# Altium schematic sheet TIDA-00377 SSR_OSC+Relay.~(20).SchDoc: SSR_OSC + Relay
size 431 x 279 mm; Date: Not shown in title block; ApprovedBy: Not shown in title block; CheckedBy: Not shown in title block; Author: Not shown in title block; CompanyName: Not shown in title block; DrawnBy: Jarrod Krebs; Engineer: Not shown in title block; Organization: Not shown in title block; Address1: Not shown in title block; Address2: Not shown in title block; Address3: Not shown in title block; Address4: Not shown in title block; DocumentNumber: 1; Revision: Use project parameter SCH_Rev; SheetNumber: 2; SheetTotal: 3; PageSetup: Record=PageOptions¦CenterHorizontal=True¦CenterVertical=True¦PrintScale=0.62¦XCorrection=1.00¦YCorrection=1.00¦PrintKind=0¦BorderSize=5000000¦LeftOffset=0¦BottomOffset=0¦Orientation=2¦PaperLength=1000¦PaperWidth=1000¦Scale=100¦PaperSource=15¦PrintQuality=-3¦MediaType=1¦DitherType=10¦PrintScaleMode=1¦PaperKind=Letter¦PaperIndex=1
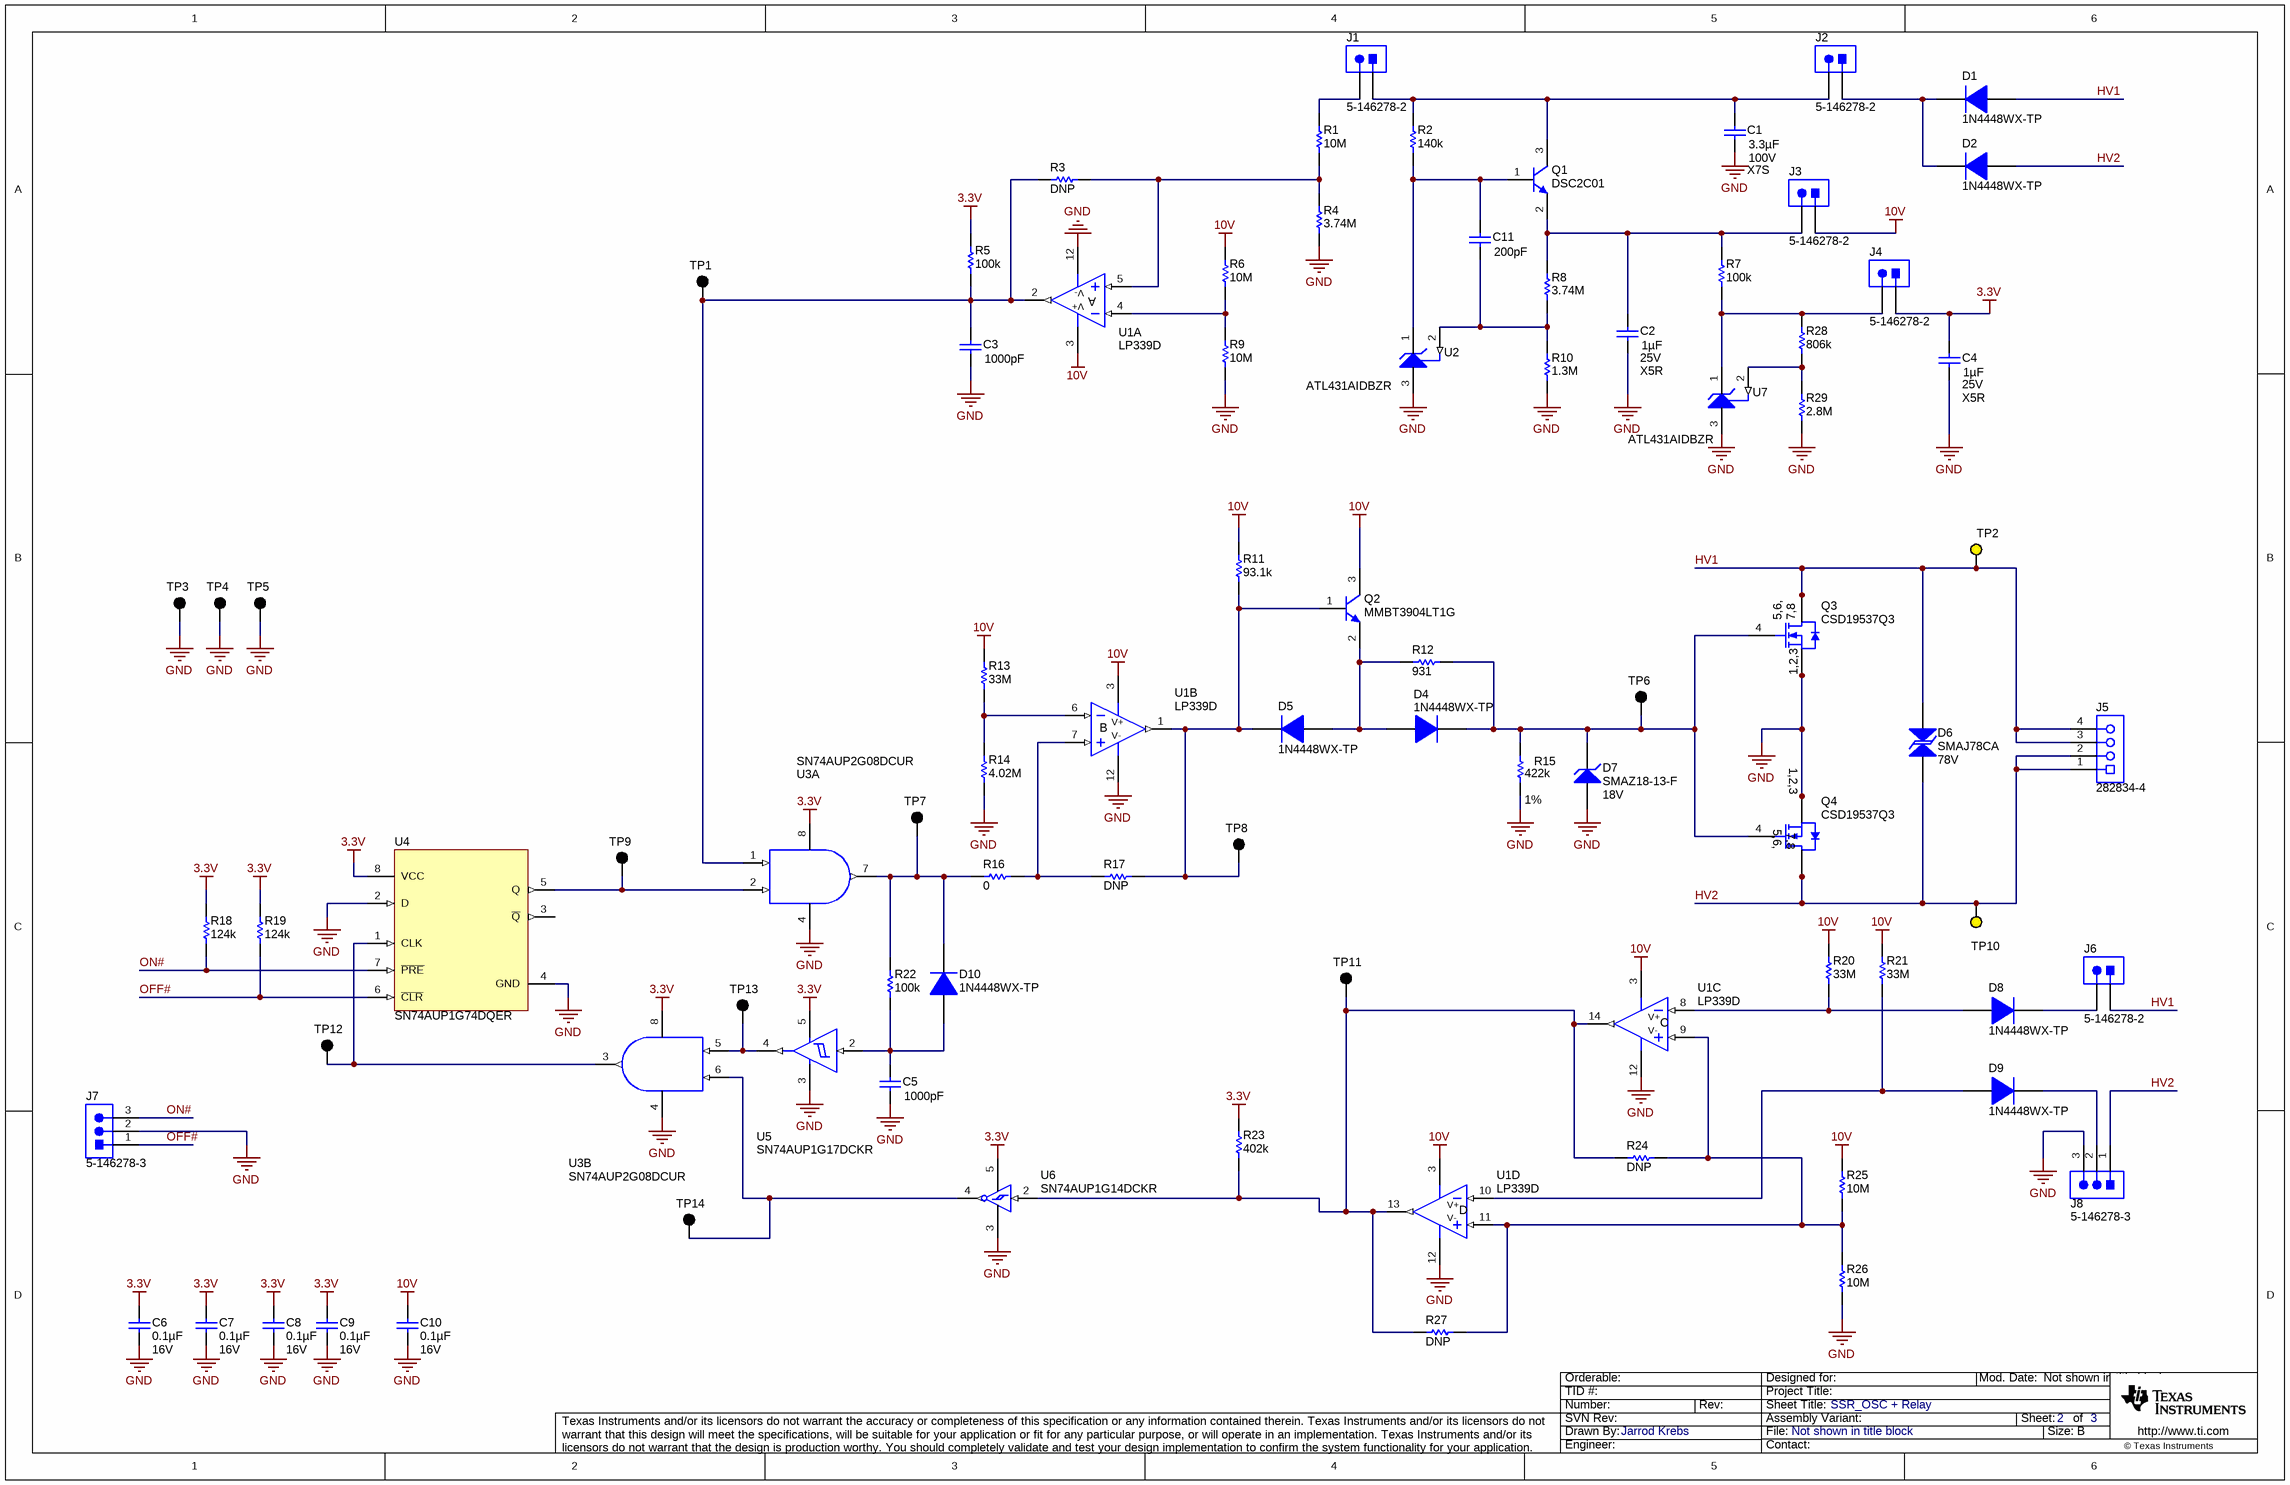
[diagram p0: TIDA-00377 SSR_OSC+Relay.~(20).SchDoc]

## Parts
C1  ValueDisplayed: 3.3µF  VDC_V: 100V  TempCo: X7S  [0603]  (hidden comment: GRM188R61E105KA12D)
C2  ValueDisplayed: 1µF  Value2: 25V  TempCo: X5R  [0603]  (hidden comment: GRM188R61E105KA12D)
C3  ValueDisplayed: 1000pF  [0603]  (hidden comment: GRM188R61E105KA12D)
C4  ValueDisplayed: 1µF  Value2: 25V  TempCo: X5R  [0603]  (hidden comment: GRM188R61E105KA12D)
C5  ValueDisplayed: 1000pF  [0603]  (hidden comment: GRM188R61E105KA12D)
C6  ValueDisplayed: 0.1µF  Value2: 16V  [0603]  (hidden comment: GRM188R71C104KA01D)
C7  ValueDisplayed: 0.1µF  Value2: 16V  [0603]  (hidden comment: GRM188R71C104KA01D)
C8  ValueDisplayed: 0.1µF  Value2: 16V  [0603]  (hidden comment: GRM188R71C104KA01D)
C9  ValueDisplayed: 0.1µF  Value2: 16V  [0603]  (hidden comment: GRM188R71C104KA01D)
C10  ValueDisplayed: 0.1µF  Value2: 16V  [0603]  (hidden comment: GRM188R71C104KA01D)
C11  ValueDisplayed: 200pF  [0603]  (hidden comment: GRM188R61E105KA12D)
D1  1N4448WX-TP  [sod-323]
D2  1N4448WX-TP  [sod-323]
D4  1N4448WX-TP  [sod-323]
D5  1N4448WX-TP  [sod-323]
D6  SMAJ78CA  value 78V  [SMA]
D7  SMAZ18-13-F  value 18V  [SMA]
D8  1N4448WX-TP  [sod-323]
D9  1N4448WX-TP  [sod-323]
D10  1N4448WX-TP  [sod-323]
J1  5-146278-2  [TE_5-146278-2]
J2  5-146278-2  [TE_5-146278-2]
J3  5-146278-2  [TE_5-146278-2]
J4  5-146278-2  [TE_5-146278-2]
J5  282834-4  [TEC_282834-4]
J6  5-146278-2  [TE_5-146278-2]
J7  5-146278-3  [TE_5-146278-3]
J8  5-146278-3  [TE_5-146278-3]
Q1  DSC2C01  [SOT-23]
Q2  MMBT3904LT1G  [SOT-23]
Q3  CSD19537Q3  [DQG0008A]
Q4  CSD19537Q3  [DQG0008A]
R1  ValueDisplayed: 10M  [0805_HV]  (hidden comment: CRCW08050000Z0EA)
R2  ValueDisplayed: 140k  [0805_HV]  (hidden comment: CRCW08050000Z0EA)
R3  ValueDisplayed: DNP  [0805_HV]  (hidden comment: CRCW08050000Z0EA)
R4  ValueDisplayed: 3.74M  [0805_HV]  (hidden comment: CRCW08050000Z0EA)
R5  ValueDisplayed: 100k  [0805_HV]  (hidden comment: CRCW08050000Z0EA)
R6  ValueDisplayed: 10M  [0805_HV]  (hidden comment: CRCW08050000Z0EA)
R7  ValueDisplayed: 100k  [0805_HV]  (hidden comment: CRCW08050000Z0EA)
R8  ValueDisplayed: 3.74M  [0805_HV]  (hidden comment: CRCW08050000Z0EA)
R9  ValueDisplayed: 10M  [0805_HV]  (hidden comment: CRCW08050000Z0EA)
R10  ValueDisplayed: 1.3M  [0805_HV]  (hidden comment: CRCW08050000Z0EA)
R11  ValueDisplayed: 93.1k  [0805_HV]  (hidden comment: CRCW08050000Z0EA)
R12  ValueDisplayed: 931  [0805_HV]  (hidden comment: CRCW08050000Z0EA)
R13  ValueDisplayed: 33M  [0805_HV]  (hidden comment: CRCW08050000Z0EA)
R14  ValueDisplayed: 4.02M  [0805_HV]  (hidden comment: CRCW08050000Z0EA)
R15  ValueDisplayed: 422k  Value1: 1%  [0805_HV]  (hidden comment: CRCW0805422KFKEA)
R16  ValueDisplayed: 0  [0805_HV]  (hidden comment: CRCW08050000Z0EA)
R17  ValueDisplayed: DNP  [0805_HV]  (hidden comment: CRCW08050000Z0EA)
R18  ValueDisplayed: 124k  [0402]  (hidden comment: CRCW0402100KJNED)
R19  ValueDisplayed: 124k  [0402]  (hidden comment: CRCW0402100KJNED)
R20  ValueDisplayed: 33M  [0805_HV]  (hidden comment: CRCW08050000Z0EA)
R21  ValueDisplayed: 33M  [0805_HV]  (hidden comment: CRCW08050000Z0EA)
R22  ValueDisplayed: 100k  [0805_HV]  (hidden comment: CRCW08050000Z0EA)
R23  ValueDisplayed: 402k  [0805_HV]  (hidden comment: CRCW08050000Z0EA)
R24  ValueDisplayed: DNP  [0805_HV]  (hidden comment: CRCW08050000Z0EA)
R25  ValueDisplayed: 10M  [0805_HV]  (hidden comment: CRCW08050000Z0EA)
R26  ValueDisplayed: 10M  [0805_HV]  (hidden comment: CRCW08050000Z0EA)
R27  ValueDisplayed: DNP  [0805_HV]  (hidden comment: CRCW08050000Z0EA)
R28  ValueDisplayed: 806k  [0805_HV]  (hidden comment: CRCW08050000Z0EA)
R29  ValueDisplayed: 2.8M  [0805_HV]  (hidden comment: CRCW08050000Z0EA)
TP1  5001  [Keystone5001]  (value not drawn)
TP2  5004  [Keystone5004]  (value not drawn)
TP3  5001  [Keystone5001]  (value not drawn)
TP4  5001  [Keystone5001]  (value not drawn)
TP5  5001  [Keystone5001]  (value not drawn)
TP6  5001  [Keystone5001]  (value not drawn)
TP7  5001  [Keystone5001]  (value not drawn)
TP8  5001  [Keystone5001]  (value not drawn)
TP9  5001  [Keystone5001]  (value not drawn)
TP10  5004  [Keystone5004]  (value not drawn)
TP11  5001  [Keystone5001]  (value not drawn)
TP12  5001  [Keystone5001]  (value not drawn)
TP13  5001  [Keystone5001]  (value not drawn)
TP14  5001  [Keystone5001]  (value not drawn)
U1  LP339D  [D0014A_N]  (parts A,B,C,D of 4)
U2  ATL431AIDBZR  [DBZ0003A_M]
U3  SN74AUP2G08DCUR  [DCU0008A_N]  (parts A,B of 2)
U4  SN74AUP1G74DQER  [DQE0008A]
U5  SN74AUP1G17DCKR  [DCK0005A_N]
U6  SN74AUP1G14DCKR  [DCK0005A_N]
U7  ATL431AIDBZR  [DBZ0003A_M]

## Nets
3.3V: C4.2 C6.2 C7.2 C8.2 C9.2 J4.1 R5.1 R18.2 R19.2 R23.1 U3.8(V+) U4.8(VCC) U5.5(VCC) U6.5(VCC)
10V: C10.2 J3.1 Q2.3(C) R6.1 R11.1 R13.1 R20.1 R21.1 R25.1 U1.3(V+)
GND: C1.1 C2.1 C3.1 C4.1 C5.1 C6.1 C7.1 C8.1 C9.1 C10.1 D7.2(A) J7.2 J8.3 Q3.1(S) Q3.2(S) Q3.3(S) Q4.1(S) Q4.2(S) Q4.3(S) R4.2 R9.2 R10.2 R14.2 R15.1 R26.2 R29.2 TP3.1 TP4.1 TP5.1 U1.12(V-) U2.3(ANODE) U3.4(V-) U4.2(D) U4.4(GND) U5.3(GND) U6.3(GND) U7.3(ANODE)
HV1: D1.2(A) D6.2 J5.3 J5.4 J6.1 Q3.5(D) Q3.6(D) Q3.7(D) Q3.8(D) Q3.9(D) TP2.1
HV2: D2.2(A) D6.1 J5.1 J5.2 J8.1 Q4.5(D) Q4.6(D) Q4.7(D) Q4.8(D) Q4.9(D) TP10.1
OFF#: J7.1 R19.1 U4.6(~{CLR})
ON#: J7.3 R18.1 U4.7(~{PRE})
NetC1_2: C1.2 J1.1 J2.2 Q1.3(C) R2.1
NetC2_2: C2.2 J3.2 Q1.2(E) R7.1 R8.1
NetC3_2: C3.2 R3.1 R5.2 TP1.1 U1.2(OUT1) U3.1(1A)
NetC5_2: C5.2 D10.2(A) R22.2 U5.2(A)
NetC11_1: C11.1 R8.2 R10.1 U2.2(REF)
NetC11_2: C11.2 Q1.1(B) R2.2 U2.1(CATHODE)
NetD1_1: D1.1(K) D2.1(K) J2.1
NetD4_1: D4.1(K) D7.1(K) Q3.4(G) Q4.4(G) R12.2 R15.2 TP6.1
NetD4_2: D4.2(A) D5.2(A) Q2.2(E) R12.1
NetD5_1: D5.1(K) Q2.1(B) R11.2 R17.2 TP8.1 U1.1(OUT2)
NetD8_1: D8.1(K) J6.2
NetD8_2: D8.2(A) R20.2 U1.8(-IN3)
NetD9_1: D9.1(K) J8.2
NetD9_2: D9.2(A) R21.2 U1.10(-IN4)
NetD10_1: D10.1(K) R16.1 R22.1 TP7.1 U3.7(1Y)
NetJ1_2: J1.2 R1.1
NetJ4_2: J4.2 R7.2 R28.1 U7.1(CATHODE)
NetR1_2: R1.2 R3.2 R4.1 U1.5(+IN1)
NetR6_2: R6.2 R9.1 U1.4(-IN1)
NetR13_2: R13.2 R14.1 U1.6(-IN2)
NetR16_2: R16.2 R17.1 U1.7(+IN2)
NetR23_2: R23.2 R24.1 R27.1 TP11.1 U1.13(OUT4) U1.14(OUT3) U6.2(A)
NetR24_2: R24.2 R25.2 R26.1 R27.2 U1.9(+IN3) U1.11(+IN4)
NetR28_2: R28.2 R29.1 U7.2(REF)
NetTP9_1: TP9.1 U3.2(1B) U4.5(Q)
NetTP12_1: TP12.1 U3.3(2Y) U4.1(CLK)
NetTP13_1: TP13.1 U3.5(2A) U5.4(Y)
NetTP14_1: TP14.1 U3.6(2B) U6.4(Y)

Not connected (* = marked no-connect by the designer): U4 3(~{Q})

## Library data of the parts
C1 = GRM188R61E105KA12D: CAP, CERM, 3.3 µF, 100 V, +/- 10%, X5R, 0603; Manufacturer: MuRata; Polarized: N; CompType: Capacitor; Value: 1uF; U/M: EA; Cap_F: 0.000001; Tolerance_%: 10; Value1: Unknown; TaMin_C: -55; TaMax_C: 85; AEC Category: Q200
C2 C4 = GRM188R61E105KA12D: CAP, CERM, 1 µF, 25 V, +/- 10%, X5R, 0603; Manufacturer: MuRata; Polarized: N; CompType: Capacitor; Value: 1uF; U/M: EA; Cap_F: 0.000001; Tolerance_%: 10; Value1: Unknown; VDC_V: 25; TaMin_C: -55; TaMax_C: 85; AEC Category: Q200
C3 C5 C11 = GRM188R61E105KA12D: CAP, CERM, 1 µF, 25 V, +/- 10%, X5R, 0603; Manufacturer: MuRata; Polarized: N; CompType: Capacitor; Value: 1uF; U/M: EA; Cap_F: 0.000001; Tolerance_%: 10; Value1: Unknown; VDC_V: 25; Value2: 25V; TaMin_C: -55; TaMax_C: 85; AEC Category: Q200
C6-C10 = GRM188R71C104KA01D: CAP, CERM, 0.1 µF, 16 V, +/- 10%, X7R, 0603; Manufacturer: MuRata; Polarized: N; CompType: Capacitor; Value: 0.1uF; U/M: EA; Cap_F: 0.0000001; Tolerance_%: 10; Value1: Unknown; VDC_V: 16; TaMin_C: -55; TaMax_C: 125; AEC Category: Q200
D1 D2 D4 D5 D8-D10 = 1N4448WX-TP: Diode, Switching, 75 V, 0.25 A, SOD-323; Manufacturer: Micro Commercial Components; U/M: EA; Value: 75V; Value1: 0.25A; Io_A: 0.25; Vr_V: 75; TJmax_C: 150; AEC Category: Q101
D6 = SMAJ78CA: Diode, TVS, Bi, 78 V, 400 W, SMA; Manufacturer: Littelfuse; U/M: EA; Power_W: 400; Vr_V: 78; Value1: 400W; RJA_CperW: 120; AEC Category: Q101
D7 = SMAZ18-13-F: Diode, Zener, 18 V, 1 W, AEC-Q101, SMA; Manufacturer: Diodes Inc.; SymbolCreator: a0412235; U/M: EA; Power_W: 1; Vz_V: 18; Value1: 1W; RJA_CperW: 125; AEC Category: Q101; AEC Qualified: Y
J1-J4 J6 = 5-146278-2: Header, 100mil, 2x1, Tin, TH; Manufacturer: TE Connectivity; SymbolCreator: a0412235; U/M: EA
J5 = 282834-4: Terminal Block, 100mil, 4X1 TH; Manufacturer: TE Connectivity; SymbolCreator: a0411947
J7 J8 = 5-146278-3: Header, 100mil, 3x1, Tin, TH; Manufacturer: TE Connectivity; SymbolCreator: a0799628
Q1 = MMBT2222A, Fairchild Semiconductor: Transistor, NPN, 40 V, 0.15 A, SOT-23; CompType: BJT; PNP: 0; NPN: 1; Vceo_V: 40; Vcesat1_V: 0.3; Value: 40 V; IcRated_A: 0.15; Value1: 0.15 A; HfeMax: 300; TaMin_C: -55; TaMax_C: 150; U/M: EA; AEC Category: Q101
Q2 = MMBT3904LT1G, ON Semiconductor: Transistor, NPN, 40 V, 0.2 A, SOT-23; CompType: BJT; PNP: 0; NPN: 1; Vceo_V: 40; Vcesat1_V: 0.3; Value: 40 V; IcRated_A: 0.2; Value1: 0.2 A; HfeMax: 300; TaMin_C: -55; TaMax_C: 150; U/M: EA; AEC Category: Q101
Q3 Q4 = CSD19537Q3: MOSFET, N-CH, 100 V, 50 A, DQG0008A; Manufacturer: Texas Instruments; Alternate Manufacturer: None; U/M: EA; ChType: N; Value: 100V; VdsMax_V: 100; Value1: ? ohm; Value2: 16 nC; QgTyp_nC: 16; Vgs_V: 20; IdsMax_A: 50; AEC Category: Q101
R1-R14 R16 R17 R20-R29 = CRCW08050000Z0EA: RES, 0, 5%, 0.125 W, 0805; Manufacturer: Vishay-Dale; CompType: Resistor; Value: 0; Value_Code: 0000; Tolerance_%: 5; Power_W: 0.125; Value2: 0.125W; VDC_V: 150; TempCo: 200 ppm/C; EIA_Code: E24; U/M: EA; AEC Category: Q200
R15 = CRCW0805422KFKEA: RES, 422 k, 1%, 0.125 W, 0805; Manufacturer: Vishay-Dale; CompType: Resistor; Value: 422k; Res_ohm: 422000; Tolerance_%: 1; Power_W: 0.125; Value2: 0.125W; VDC_V: 150; TempCo: 100 ppm/C; EIA_Code: E96; U/M: EA; AEC Category: Q200
R18 R19 = CRCW0402100KJNED: RES, 100 k, 5%, 0.063 W, 0402; Manufacturer: Vishay-Dale; CompType: Resistor; Value: 100k; Res_ohm: 100000; Tolerance_%: 5; Power_W: 0.063; Value2: 0.063W; VDC_V: 50; TempCo: 200 ppm/C; EIA_Code: E24; U/M: EA; AEC Category: Q200
TP1 TP3-TP9 TP11-TP14 = 5001: Test Point, Miniature, Black, TH; Manufacturer: Keystone; CompType: Test Point Loop; U/M: EA
TP2 TP10 = 5004: Test Point, Miniature, Yellow, TH; Manufacturer: Keystone; CompType: Test Point Loop; U/M: EA
U1 = LP339D: Quad, Low-Power, General Purpose Differential Comparator, D0014A; Manufacturer: Texas Instruments; SymbolCreator: Altium; CompType: OpAmp IC
U2 U7 = ATL431AIDBZR: 2.5V Low Iq Adjustable Precision Shunt Regulator, DBZ0003A; Manufacturer: Texas Instruments; SymbolCreator: a0412235; CompType: IC; U/M: EA
U3 = SN74AUP2G08DCUR: LOW-POWER DUAL 2-INPUT POSITIVE-AND GATE, DCU0008A; Manufacturer: Texas Instruments; SymbolCreator: Altium; CompType: IC; U/M: EA
U4 = SN74AUP1G74DQER: LOW-POWER SINGLE POSITIVE-EDGE-TRIGGERED D-TYPE FLIP-FLOP WITH CLEAR AND PRESET, DQE0008A; Manufacturer: Texas Instruments; SymbolCreator: a0799628; CompType: IC; U/M: EA
U5 = SN74LVC1G17DCKR: SINGLE SCHMITT-TRIGGER BUFFER, DCK0005A; Alternate PartNumber: SN74LVC1G17DCKT; Manufacturer: Texas Instruments; SymbolCreator: a0799628; CompType: IC; U/M: EA
U6 = SN74LVC1G14DCKR: SINGLE SCHMITT-TRIGGER INVERTER, DCK0005A; Alternate PartNumber: SN74LVC1G14DCKT; Manufacturer: Texas Instruments; SymbolCreator: a0799628; CompType: IC; U/M: EA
